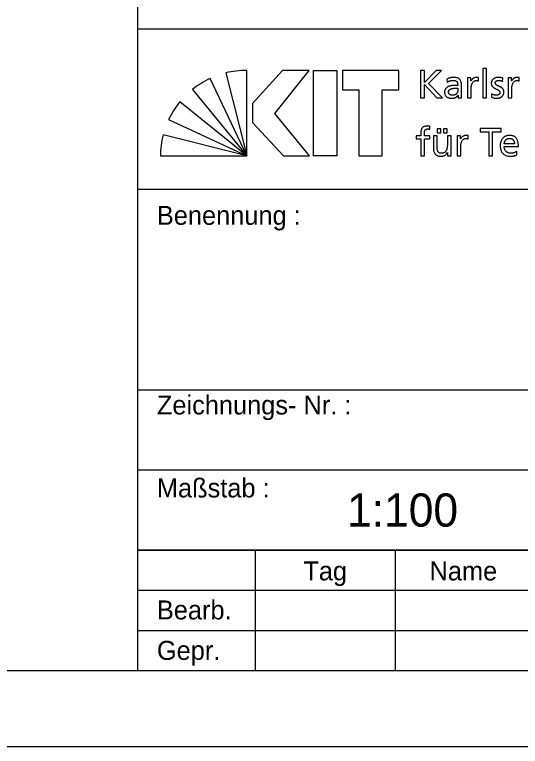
# Model space of a CAD drawing. Extents: x 0 to 42, y 0 to 29.7.
# Drawn here: x 31.5 to 36.83, y 0 to 7.72 of the extents above; entities that cross this region are included whole.
import ezdxf

# ---------------------------------------------------------------- set-up
doc = ezdxf.new("R2010")
doc.units = 0
doc.layers.add('90_Plankopf', color=7, linetype='Continuous')

msp = doc.modelspace()

# ---------------------------------------------------------------- linework, layer by layer
at = {"layer": '90_Plankopf'}
for p, q in [((32.8001, 7.568), (32.8001, 8.837)), ((32.8001, 7.568), (41.2, 7.568)), ((33.7275, 7.1023), (33.9481, 6.2276)), ((33.9481, 6.2276), (33.9481, 7.1274)), ((35.781, 7.1276), (35.781, 6.8396)), ((33.9481, 6.2276), (33.5633, 7.0442)), ((36.0579, 7.0352), (36.06, 7.0022)), ((36.3926, 7.0174), (36.3926, 7.0521)), ((36.6457, 7.0129), (36.649, 7.0468)), ((36.8211, 7.0174), (36.8211, 7.0521)), ((36.2118, 6.8808), (36.2118, 6.9679)), ((33.3744, 6.9275), (33.9481, 6.2276)), ((36.173, 6.9399), (36.173, 6.9213)), ((36.5297, 6.8808), (36.5277, 6.8462)), ((33.9481, 6.2276), (33.2434, 6.7976)), ((35.781, 6.8396), (35.8222, 6.8396)), ((35.9506, 6.8396), (36.0108, 6.8396)), ((33.124, 6.6103), (33.9481, 6.2276)), ((35.8773, 6.5083), (35.879, 6.5396)), ((33.9481, 6.2276), (33.0658, 6.4478)), ((36.2827, 6.4055), (36.2827, 6.4402)), ((36.7706, 6.3531), (36.6616, 6.3531)), ((36.6616, 6.3242), (36.8119, 6.3242)), ((36.7958, 6.2363), (36.7958, 6.2751)), ((33.0364, 6.2276), (33.9481, 6.2276)), ((32.8001, 5.876), (41.2, 5.876)), ((32.8001, 3.761), (41.2, 3.761)), ((32.8001, 2.915), (41.2, 2.915)), ((32.8001, 2.069), (41.2, 2.069)), ((32.8001, 2.069), (41.2, 2.069)), ((32.8001, 2.069), (41.2, 2.069)), ((32.8001, 2.069), (41.2, 2.069)), ((32.8001, 0.8), (32.8001, 2.069)), ((34.0353, 2.069), (34.0353, 0.8)), ((35.5177, 0.8), (35.5177, 2.069)), ((32.8001, 1.646), (37, 1.646)), ((32.8001, 1.223), (37, 1.223)), ((32.8001, 0.8), (41.2, 0.8)), ((32.8001, 0.8), (41.1999, 0.8))]:
    msp.add_line(p, q, dxfattribs=at)
for points in [[(0, 0), (42, 0), (42, 29.7), (0, 29.7)], [(0.8, 0.8), (41.2, 0.8), (41.2, 28.9), (0.8, 28.9)], [(34.6066, 7.1276), (34.3236, 7.1276), (34.0073, 6.7789), (34.0073, 6.5782), (34.3338, 6.2276), (34.6085, 6.2276), (34.2422, 6.6753)], [(34.897, 7.1276), (34.897, 6.2276), (34.6501, 6.2276), (34.6501, 7.1276)], [(34.9562, 7.1276), (34.9562, 6.925), (35.1301, 6.925), (35.1301, 6.2276), (35.3771, 6.2276), (35.3771, 6.925), (35.551, 6.925), (35.551, 7.1276)]]:
    msp.add_lwpolyline(points, close=True, dxfattribs=at)
for points in [[(32.8001, 2.069), (32.8001, 7.568)], [(36.0108, 6.8396), (35.8647, 6.9914), (36.0001, 7.1276), (35.9452, 7.1276), (35.8222, 7.0009), (35.8222, 7.1276), (35.781, 7.1276)], [(36.4381, 6.8396), (36.4768, 6.8396), (36.4768, 7.1491), (36.4381, 7.1491), (36.4381, 6.8396)], [(36.3122, 7.0174), (36.3113, 7.0174), (36.3113, 7.05), (36.275, 7.05), (36.275, 6.8396), (36.3138, 6.8396), (36.3138, 6.9353)], [(36.7407, 7.0174), (36.7398, 7.0174), (36.7398, 7.05), (36.7035, 7.05), (36.7035, 6.8396), (36.7423, 6.8396), (36.7423, 6.9353)], [(35.8222, 6.8396), (35.8222, 6.9807), (35.9506, 6.8396)], [(36.1763, 6.8668), (36.1772, 6.8668), (36.1772, 6.8396), (36.2135, 6.8396)], [(35.9554, 6.5116), (35.9554, 6.4703), (35.9942, 6.4703), (35.9942, 6.5116), (35.9554, 6.5116)], [(36.0231, 6.5116), (36.0231, 6.4703), (36.0619, 6.4703), (36.0619, 6.5116), (36.0231, 6.5116)], [(36.499, 6.2276), (36.5403, 6.2276), (36.5403, 6.4794), (36.6298, 6.4794), (36.6298, 6.5157), (36.4094, 6.5157), (36.4094, 6.4794), (36.499, 6.4794), (36.499, 6.2276)], [(35.7824, 6.4575), (35.7824, 6.4381), (35.7329, 6.4381), (35.7329, 6.4068), (35.7824, 6.4068), (35.7824, 6.2276), (35.8212, 6.2276), (35.8212, 6.4068), (35.8769, 6.4068), (35.8769, 6.4381), (35.8212, 6.4381), (35.8212, 6.4608)], [(35.9542, 6.3292), (35.9542, 6.4381), (35.9154, 6.4381), (35.9154, 6.3131)], [(36.1015, 6.2276), (36.1015, 6.4381), (36.0627, 6.4381), (36.0627, 6.3407)], [(36.2022, 6.4055), (36.2014, 6.4055), (36.2014, 6.4381), (36.1651, 6.4381), (36.1651, 6.2276), (36.2039, 6.2276), (36.2039, 6.3234)], [(36.0631, 6.2611), (36.0639, 6.2611), (36.0639, 6.2276), (36.1015, 6.2276)], [(41.2, 2.069), (32.8001, 2.069)], [(32.8001, 2.069), (32.8001, 2.069)], [(32.8001, 0.8), (41.2, 0.8)]]:
    msp.add_lwpolyline(points, dxfattribs=at)
for centre, start, end in [((33.9449, 6.1746), 89.80527, 103.18947), ((33.9662, 6.1808), 115.01261, 128.3968), ((33.9816, 6.1953), 140.78977, 154.17397), ((33.9891, 6.2128), 165.72225, 179.10644)]:
    msp.add_arc(centre, 0.9528, start, end, dxfattribs=at)
for points in [[(36.2118, 6.9679), (36.2119, 6.987), (36.2091, 7.0031), (36.2033, 7.016), (36.1975, 7.0289), (36.1884, 7.0386), (36.1759, 7.0452), (36.1635, 7.0517), (36.1472, 7.055), (36.1272, 7.055), (36.1138, 7.0549), (36.1014, 7.0531), (36.0898, 7.0494), (36.0782, 7.0458), (36.0676, 7.0411), (36.0579, 7.0352)], [(36.06, 7.0022), (36.0653, 7.0066), (36.0713, 7.0104), (36.0779, 7.0136), (36.0846, 7.0168), (36.0916, 7.0193), (36.099, 7.021), (36.1063, 7.0228), (36.1137, 7.0236), (36.121, 7.0236), (36.1339, 7.0236), (36.1441, 7.0216), (36.1518, 7.0175), (36.1594, 7.0134), (36.1649, 7.0073), (36.1682, 6.9992), (36.1715, 6.9909), (36.1731, 6.9808), (36.173, 6.9687)], [(36.3926, 7.0521), (36.3899, 7.0527), (36.3873, 7.0531), (36.3849, 7.0536), (36.3824, 7.054), (36.3798, 7.0544), (36.3769, 7.0546), (36.3741, 7.0549), (36.3708, 7.055), (36.367, 7.055), (36.3595, 7.0549), (36.3523, 7.0533), (36.3452, 7.0501), (36.3382, 7.0469), (36.3318, 7.0426), (36.3261, 7.0369), (36.3203, 7.0313), (36.3157, 7.0248), (36.3122, 7.0174)], [(36.649, 7.0468), (36.6414, 7.0491), (36.6337, 7.051), (36.6259, 7.0526), (36.6181, 7.0541), (36.6097, 7.0549), (36.6007, 7.055), (36.5903, 7.055), (36.5805, 7.0537), (36.5716, 7.051), (36.5625, 7.0484), (36.5547, 7.0443), (36.548, 7.039), (36.5412, 7.0337), (36.5359, 7.0269), (36.5322, 7.0188), (36.5284, 7.0107), (36.5265, 7.0011), (36.5264, 6.9902), (36.5265, 6.9818), (36.5282, 6.9746), (36.5315, 6.9684), (36.5347, 6.9623), (36.5391, 6.957), (36.5445, 6.9524), (36.55, 6.948), (36.5559, 6.944), (36.5623, 6.9405), (36.5688, 6.937), (36.5753, 6.9337), (36.5817, 6.9307), (36.5882, 6.9276), (36.5942, 6.9245), (36.5995, 6.9212), (36.605, 6.918), (36.6093, 6.9144), (36.6126, 6.9103), (36.6158, 6.9063), (36.6176, 6.9015), (36.6176, 6.8961), (36.6176, 6.8905), (36.6163, 6.8857), (36.6139, 6.8818), (36.6116, 6.878), (36.6084, 6.8749), (36.6045, 6.8725), (36.6006, 6.8702), (36.5963, 6.8685), (36.5917, 6.8675), (36.5871, 6.8665), (36.5825, 6.866), (36.578, 6.866), (36.5742, 6.866), (36.5695, 6.8665), (36.5639, 6.8676), (36.5584, 6.8687), (36.5526, 6.8704), (36.5466, 6.8726), (36.5405, 6.8748), (36.535, 6.8775), (36.5297, 6.8808)], [(36.5277, 6.8462), (36.5366, 6.8416), (36.546, 6.8384), (36.5558, 6.8368), (36.5656, 6.8352), (36.5755, 6.8345), (36.5854, 6.8346), (36.5949, 6.8346), (36.604, 6.8359), (36.6127, 6.8385), (36.6215, 6.8412), (36.6293, 6.8452), (36.6363, 6.8506), (36.6431, 6.8559), (36.6487, 6.8628), (36.6527, 6.871), (36.6568, 6.8793), (36.6588, 6.889), (36.6589, 6.9002), (36.6588, 6.9098), (36.6571, 6.9179), (36.6539, 6.9246), (36.6506, 6.9312), (36.6462, 6.9369), (36.6408, 6.9416), (36.6354, 6.9462), (36.6295, 6.9501), (36.623, 6.9535), (36.6165, 6.9568), (36.6101, 6.9599), (36.6036, 6.9627), (36.5971, 6.9656), (36.5912, 6.9685), (36.5858, 6.9716), (36.5804, 6.9748), (36.576, 6.9785), (36.5727, 6.9826), (36.5695, 6.9869), (36.5678, 6.992), (36.5677, 6.9981), (36.5678, 7.0038), (36.5696, 7.0086), (36.5729, 7.0124), (36.5763, 7.0162), (36.5808, 7.019), (36.5864, 7.0209), (36.592, 7.0228), (36.5982, 7.0236), (36.6048, 7.0236), (36.6072, 7.0236), (36.6102, 7.0233), (36.6139, 7.0228), (36.6175, 7.0221), (36.6213, 7.0213), (36.6254, 7.0203), (36.6295, 7.0193), (36.6333, 7.0181), (36.6369, 7.0168), (36.6405, 7.0156), (36.6434, 7.0143), (36.6457, 7.0129)], [(36.8211, 7.0521), (36.8184, 7.0527), (36.8158, 7.0531), (36.8134, 7.0536), (36.811, 7.054), (36.8083, 7.0544), (36.8054, 7.0546), (36.8026, 7.0549), (36.7993, 7.055), (36.7955, 7.055), (36.788, 7.0549), (36.7808, 7.0533), (36.7737, 7.0501), (36.7667, 7.0469), (36.7603, 7.0426), (36.7546, 7.0369), (36.7488, 7.0313), (36.7442, 7.0248), (36.7407, 7.0174)], [(36.173, 6.9687), (36.168, 6.969), (36.1633, 6.9692), (36.1589, 6.9693), (36.1546, 6.9694), (36.1502, 6.9695), (36.1459, 6.9696), (36.1415, 6.9696), (36.1368, 6.9696), (36.1318, 6.9696), (36.1237, 6.9696), (36.1151, 6.9689), (36.1063, 6.9674), (36.0973, 6.966), (36.0886, 6.9637), (36.0801, 6.9604), (36.0715, 6.9571), (36.0638, 6.9528), (36.0569, 6.9475), (36.0499, 6.9421), (36.0444, 6.9355), (36.0403, 6.9278), (36.0362, 6.9199), (36.0341, 6.9108), (36.034, 6.9002), (36.0341, 6.885), (36.0374, 6.8725), (36.0439, 6.8629), (36.0504, 6.8532), (36.0594, 6.846), (36.071, 6.8414), (36.0825, 6.8369), (36.0959, 6.8346), (36.1111, 6.8346), (36.12, 6.8347), (36.128, 6.8358), (36.135, 6.8379), (36.1421, 6.8399), (36.1483, 6.8426), (36.1536, 6.8459), (36.159, 6.8492), (36.1635, 6.8527), (36.1673, 6.8564), (36.171, 6.8601), (36.1741, 6.8635), (36.1763, 6.8668)], [(36.3138, 6.9353), (36.3139, 6.953), (36.3163, 6.9683), (36.321, 6.9811), (36.3257, 6.9939), (36.3323, 7.0038), (36.3409, 7.0106), (36.3494, 7.0176), (36.3595, 7.0211), (36.3712, 7.0211), (36.3746, 7.0212), (36.378, 7.0209), (36.3818, 7.0204), (36.3855, 7.0199), (36.3891, 7.0189), (36.3926, 7.0174)], [(36.7423, 6.9353), (36.7424, 6.953), (36.7448, 6.9683), (36.7495, 6.9811), (36.7542, 6.9939), (36.7608, 7.0038), (36.7694, 7.0106), (36.7779, 7.0176), (36.788, 7.0211), (36.7997, 7.0211), (36.803, 7.0212), (36.8065, 7.0209), (36.8103, 7.0204), (36.814, 7.0199), (36.8175, 7.0189), (36.8211, 7.0174)], [(36.173, 6.9213), (36.173, 6.9108), (36.1708, 6.9013), (36.1664, 6.893), (36.162, 6.8847), (36.1554, 6.8782), (36.1467, 6.8733), (36.138, 6.8685), (36.1272, 6.866), (36.1144, 6.866), (36.11, 6.866), (36.1054, 6.8668), (36.1008, 6.8682), (36.0963, 6.8697), (36.092, 6.8718), (36.0882, 6.8747), (36.0843, 6.8777), (36.0812, 6.8813), (36.0789, 6.8855), (36.0765, 6.8897), (36.0753, 6.8947), (36.0752, 6.9002), (36.0754, 6.9076), (36.0772, 6.9138), (36.0808, 6.9187), (36.0844, 6.9236), (36.0891, 6.9276), (36.0949, 6.9305), (36.1007, 6.9335), (36.1069, 6.9357), (36.1135, 6.9372), (36.1201, 6.9386), (36.1265, 6.9396), (36.1326, 6.9401), (36.1387, 6.9405), (36.1439, 6.9407), (36.1483, 6.9407), (36.1524, 6.9407), (36.1565, 6.9405), (36.1607, 6.9403), (36.1648, 6.9401), (36.1689, 6.9399), (36.173, 6.9399)], [(36.2135, 6.8396), (36.2132, 6.8416), (36.2129, 6.8443), (36.2126, 6.8477), (36.2125, 6.8511), (36.2122, 6.8555), (36.2121, 6.8609), (36.2119, 6.8663), (36.2118, 6.8729), (36.2118, 6.8808)], [(35.879, 6.5396), (35.8751, 6.5402), (35.871, 6.5409), (35.8668, 6.5413), (35.8625, 6.5418), (35.8579, 6.5421), (35.853, 6.5421), (35.8388, 6.542), (35.827, 6.54), (35.8178, 6.5361), (35.8086, 6.5321), (35.8014, 6.5264), (35.7962, 6.519), (35.791, 6.5116), (35.7875, 6.5027), (35.7854, 6.4923), (35.7833, 6.4819), (35.7824, 6.4704), (35.7824, 6.4575)], [(35.8212, 6.4608), (35.8212, 6.468), (35.8216, 6.4746), (35.8224, 6.4806), (35.8232, 6.4867), (35.8249, 6.492), (35.8275, 6.4965), (35.83, 6.501), (35.8338, 6.5045), (35.8388, 6.5069), (35.8439, 6.5094), (35.8505, 6.5107), (35.8588, 6.5107), (35.8621, 6.5107), (35.8655, 6.5105), (35.8688, 6.5101), (35.8722, 6.5097), (35.875, 6.5091), (35.8773, 6.5083)], [(36.2827, 6.4402), (36.28, 6.4407), (36.2774, 6.4412), (36.275, 6.4417), (36.2725, 6.4421), (36.2698, 6.4424), (36.267, 6.4427), (36.2642, 6.4429), (36.2609, 6.443), (36.2571, 6.443), (36.2496, 6.443), (36.2423, 6.4414), (36.2352, 6.4382), (36.2282, 6.435), (36.2218, 6.4306), (36.2161, 6.425), (36.2104, 6.4193), (36.2057, 6.4129), (36.2022, 6.4055)], [(36.2039, 6.3234), (36.2039, 6.3411), (36.2064, 6.3563), (36.211, 6.3691), (36.2158, 6.3819), (36.2224, 6.3918), (36.231, 6.3987), (36.2395, 6.4057), (36.2496, 6.4091), (36.2612, 6.4092), (36.2646, 6.4093), (36.2681, 6.409), (36.2718, 6.4085), (36.2756, 6.4079), (36.2791, 6.4069), (36.2827, 6.4055)], [(36.8119, 6.3242), (36.8119, 6.3412), (36.8103, 6.357), (36.8072, 6.3713), (36.8041, 6.3858), (36.7989, 6.3983), (36.7918, 6.409), (36.7846, 6.4197), (36.7751, 6.4281), (36.7631, 6.434), (36.7512, 6.4399), (36.7365, 6.443), (36.719, 6.443), (36.7041, 6.443), (36.6906, 6.4404), (36.6785, 6.4352), (36.6665, 6.43), (36.6561, 6.4227), (36.6474, 6.4132), (36.6387, 6.4037), (36.6321, 6.3925), (36.6275, 6.3795), (36.6228, 6.3666), (36.6205, 6.3523), (36.6204, 6.3366), (36.6204, 6.3194), (36.6225, 6.3038), (36.6269, 6.2899), (36.6312, 6.2759), (36.6379, 6.264), (36.6469, 6.254), (36.6558, 6.2439), (36.6671, 6.2362), (36.6808, 6.2309), (36.6945, 6.2254), (36.7107, 6.2228), (36.7293, 6.2227), (36.7408, 6.2228), (36.7506, 6.2235), (36.7587, 6.225), (36.7667, 6.2265), (36.7737, 6.2283), (36.7797, 6.2304), (36.7855, 6.2324), (36.7909, 6.2344), (36.7958, 6.2363)], [(36.6616, 6.3531), (36.6623, 6.36), (36.6639, 6.3668), (36.6664, 6.3737), (36.6688, 6.3806), (36.6722, 6.3869), (36.6768, 6.3926), (36.6812, 6.3984), (36.6869, 6.4029), (36.6937, 6.4064), (36.7006, 6.4098), (36.7087, 6.4116), (36.7182, 6.4117), (36.7266, 6.4116), (36.734, 6.4101), (36.7404, 6.4071), (36.747, 6.404), (36.7524, 6.3999), (36.7569, 6.3945), (36.7614, 6.3891), (36.7648, 6.3829), (36.7671, 6.3759), (36.7694, 6.3688), (36.7706, 6.3612), (36.7706, 6.3531)], [(36.0627, 6.3407), (36.0627, 6.3279), (36.0615, 6.3161), (36.0589, 6.3055), (36.0564, 6.295), (36.0525, 6.2859), (36.0473, 6.2782), (36.0421, 6.2705), (36.0354, 6.2646), (36.0273, 6.2604), (36.0193, 6.2562), (36.0097, 6.2541), (35.9987, 6.254), (35.9875, 6.2547), (35.9786, 6.2579), (35.9721, 6.2635), (35.9656, 6.2692), (35.961, 6.2774), (35.9582, 6.2883), (35.9554, 6.2992), (35.9541, 6.3128), (35.9542, 6.3292)], [(35.9154, 6.3131), (35.9154, 6.2941), (35.9181, 6.278), (35.9237, 6.2645), (35.9293, 6.251), (35.9379, 6.2407), (35.9496, 6.2335), (35.9612, 6.2264), (35.9761, 6.2228), (35.9942, 6.2227), (36.004, 6.2228), (36.0135, 6.2243), (36.0225, 6.2273), (36.0315, 6.2304), (36.0396, 6.2348), (36.0466, 6.2405), (36.0537, 6.2462), (36.0592, 6.2531), (36.0631, 6.2611)], [(36.7958, 6.2751), (36.7933, 6.2731), (36.7899, 6.2709), (36.7852, 6.2685), (36.7806, 6.2661), (36.7754, 6.2638), (36.7694, 6.2616), (36.7634, 6.2594), (36.7572, 6.2576), (36.7506, 6.2562), (36.744, 6.2548), (36.7374, 6.2541), (36.7309, 6.254), (36.7217, 6.2541), (36.713, 6.2558), (36.7046, 6.2592), (36.6964, 6.2625), (36.6889, 6.2673), (36.6825, 6.2735), (36.6761, 6.2797), (36.671, 6.2871), (36.6673, 6.2957), (36.6636, 6.3043), (36.6617, 6.3138), (36.6616, 6.3242)]]:
    msp.add_open_spline(points, degree=3, dxfattribs=at)

# ---------------------------------------------------------------- texts
for s, height, p in [('Benennung :', 0.2, (33, 5.5)), ('Zeichnungs- Nr. :', 0.2, (33, 3.5)), ('Maßstab :', 0.2, (33, 2.625)), ('1:100   ', 0.34999, (35.0048, 2.3175)), ('Tag', 0.2, (34.5441, 1.75)), ('Name', 0.2, (35.875, 1.75)), ('Bearb.', 0.2, (33, 1.3385)), ('Gepr.', 0.2, (33, 0.9122))]:
    msp.add_text(s, height=height, dxfattribs=at).set_placement(p)

doc.saveas('drawing.dxf')
